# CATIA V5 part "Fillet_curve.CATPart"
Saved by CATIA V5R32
Part number: Part1
Bounding box of the stored display mesh (mm): x -44.747 to 47.153, y -50.22 to 55.347, z 0 to 0
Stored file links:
  D:\PROJECTS\Project 2022\CATIA V5 6R 2022\Resources\Part Files\c17_catia_v6_6r2022_prt\Fillet_curve.CATPart
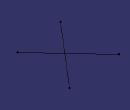
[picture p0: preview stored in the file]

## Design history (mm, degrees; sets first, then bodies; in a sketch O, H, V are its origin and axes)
Body1 (main body)
  Sketch1 on xy-plane, origin (0, 0, 0), H (1, 0, 0), V (0, 1, 0)
    line L1 (-44.7471, 47.4214) -> (39.0352, -41.3682)
    coincidence: L1 O
  Sketch2 on xy-plane, origin (0, 0, 0), H (1, 0, 0), V (0, 1, 0)
    line L1 (47.1532, 55.3475) -> (-42.7846, -50.2197)
    coincidence: L1 O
